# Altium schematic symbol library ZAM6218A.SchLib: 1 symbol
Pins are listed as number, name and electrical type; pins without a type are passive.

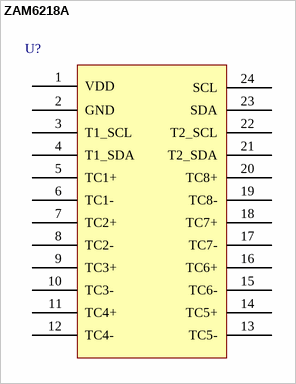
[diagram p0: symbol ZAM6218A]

## ZAM6218A
designator U?
footprint ZAM6218A
pins: 1 VDD, 2 GND, 3 T1_SCL, 4 T1_SDA, 5 TC1+, 6 TC1-, 7 TC2+, 8 TC2-, 9 TC3+, 10 TC3-, 11 TC4+, 12 TC4-, 13 TC5-, 14 TC5+, 15 TC6-, 16 TC6+, 17 TC7-, 18 TC7+, 19 TC8-, 20 TC8+, 21 T2_SDA, 22 T2_SCL, 23 SDA, 24 SCL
